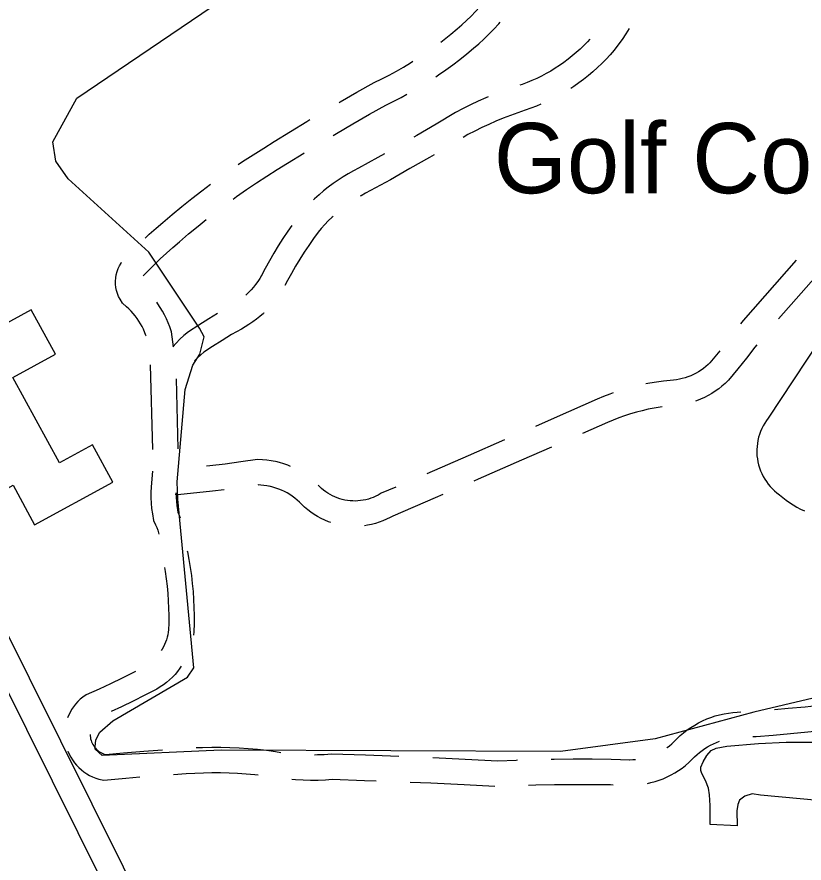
# Model space of a CAD drawing. Extents: x 3568792 to 3606828, y 529143 to 554785.
# Drawn here: x 3584735 to 3585665, y 535934 to 536934 of the extents above; entities that cross this region are included whole.
import ezdxf

# ---------------------------------------------------------------- set-up
doc = ezdxf.new("R2010")
doc.units = 0
for name, color, linetype in [('V-BLDG-IDEN', 7, 'Continuous'), ('V-BLDG-OTLN', 7, 'Continuous'), ('V-ROAD-CNTR', 7, 'Continuous'), ('V-SITE-OTLN', 7, 'Continuous'), ('V-TOPO-SHOR', 7, 'Continuous')]:
    doc.layers.add(name, color=color, linetype=linetype)

msp = doc.modelspace()

# ---------------------------------------------------------------- linework, layer by layer
at = {"layer": 'V-BLDG-OTLN'}
msp.add_lwpolyline([(3584785.2, 536406.99), (3584730.13, 536508), (3584780.53, 536535.47), (3584752.02, 536587.75), (3584649.36, 536531.78), (3584674.16, 536486.29), (3584666.89, 536482.33), (3584687.6, 536444.35), (3584659.96, 536429.28), (3584675.87, 536400.1), (3584697.16, 536411.71), (3584717.85, 536373.76), (3584730.38, 536380.59), (3584755.94, 536333.72), (3584848.35, 536384.12), (3584824.26, 536428.3)], close=True, dxfattribs=at)
at = {"layer": 'V-ROAD-CNTR'}
for p, q in [((3585700.82, 536652.21), (3585634.72, 536577.17)), ((3584892.56, 536522.77), (3584895.19, 536422.8)), ((3584923.01, 536506.15), (3584925.18, 536423.59))]:
    msp.add_line(p, q, dxfattribs=at)
for points in [[(3585235.77, 536904.14), (3585239.85, 536907.25), (3585247.44, 536913.3), (3585254.91, 536919.53), (3585260.63, 536924.48), (3585266.17, 536929.54), (3585271.57, 536934.75), (3585276.83, 536940.1), (3585281.94, 536945.59), (3585286.91, 536951.21), (3585291.73, 536956.96), (3585296.39, 536962.84), (3585300.89, 536968.84), (3585305.24, 536974.96), (3585305.43, 536975.25)], [(3585229.95, 536863.15), (3585233.17, 536865.29), (3585241.68, 536871.2), (3585250.05, 536877.3), (3585258.29, 536883.58), (3585266.4, 536890.04), (3585274.34, 536896.67), (3585280.57, 536902.07), (3585286.7, 536907.67), (3585292.68, 536913.43), (3585298.5, 536919.35), (3585304.16, 536925.42), (3585306.07, 536927.59)], [(3585458.36, 536920.27), (3585454.32, 536913.84), (3585449.86, 536907.14), (3585445.06, 536900.32), (3585440.41, 536894.57), (3585435.75, 536889.16), (3585430.93, 536883.9), (3585425.94, 536878.79), (3585420.8, 536873.84), (3585415.5, 536869.06), (3585410.06, 536864.44), (3585404.47, 536859.99), (3585398.75, 536855.72), (3585392.9, 536851.63), (3585389.24, 536849.24)], [(3585411.87, 536907.51), (3585409.13, 536904.52), (3585404.8, 536900.08), (3585400.33, 536895.79), (3585395.73, 536891.62), (3585391, 536887.61), (3585386.15, 536883.75), (3585381.19, 536880.04), (3585376.1, 536876.49), (3585370.91, 536873.11), (3585365.61, 536869.88), (3585360.22, 536866.82), (3585354.74, 536863.93), (3585349.16, 536861.21), (3585343.5, 536858.67), (3585337.77, 536856.31), (3585331.97, 536854.13), (3585329.19, 536853.19)], [(3585115.53, 536832.78), (3585116.91, 536833.58), (3585136.69, 536844.89), (3585156.88, 536856.15), (3585166.12, 536860.66), (3585174.75, 536865.11), (3585183.28, 536869.74), (3585191.7, 536874.56), (3585200.02, 536879.57), (3585202.89, 536881.38)], [(3585108.41, 536793.8), (3585112.52, 536796.26), (3585131.92, 536807.61), (3585151.44, 536818.76), (3585170.78, 536829.55), (3585179.58, 536833.84), (3585188.79, 536838.59), (3585195.77, 536842.39)], [(3585291.69, 536839.29), (3585289.05, 536838.2), (3585280, 536834.2), (3585271.04, 536830.01), (3585262.18, 536825.62), (3585253.19, 536820.9), (3585230.15, 536807.1), (3585207.41, 536793.75), (3585203.87, 536791.72)], [(3585353.95, 536830.53), (3585348.76, 536828.39), (3585342.08, 536825.89), (3585335.53, 536823.65), (3585326.62, 536820.64), (3585317.96, 536817.49), (3585309.37, 536814.15), (3585300.85, 536810.62), (3585292.42, 536806.89), (3585284.07, 536802.98), (3585275.81, 536798.89), (3585267.88, 536794.73), (3585262.16, 536791.31)], [(3584996.39, 536759.3), (3585001.62, 536762.84), (3585014.04, 536770.96), (3585026.6, 536778.88), (3585039.09, 536786.48), (3585058.26, 536798.48), (3585077.69, 536810.38), (3585081.1, 536812.42)], [(3584990.41, 536718.54), (3584994.59, 536721.57), (3585006.34, 536729.82), (3585018.23, 536737.86), (3585030.25, 536745.72), (3585042.4, 536753.38), (3585054.85, 536760.95), (3585074.05, 536772.98), (3585074.2, 536773.07)], [(3585169.1, 536771.93), (3585161.57, 536767.7), (3585138.59, 536755.05), (3585132.67, 536752.01), (3585126.47, 536748.55), (3585120.38, 536744.89), (3585114.41, 536741.03), (3585108.58, 536736.98), (3585102.88, 536732.73), (3585097.33, 536728.3), (3585091.92, 536723.7), (3585086.67, 536718.91), (3585085.49, 536717.77)], [(3585227.76, 536770.91), (3585222.47, 536767.81), (3585199.37, 536754.54), (3585176.15, 536741.48), (3585152.69, 536728.57), (3585146.84, 536725.56), (3585141.5, 536722.59), (3585140.54, 536722.01)], [(3584886.62, 536672.63), (3584891.43, 536677.08), (3584899.42, 536684.16), (3584907.4, 536690.94), (3584918.55, 536700.5), (3584929.98, 536709.98), (3584941.56, 536719.27), (3584953.28, 536728.37), (3584963.73, 536736.21)], [(3585108.49, 536698.21), (3585107.24, 536697.07), (3585102.85, 536692.8), (3585098.61, 536688.4), (3585094.52, 536683.85), (3585090.78, 536679.42), (3585085.34, 536671.88), (3585079.82, 536663.9), (3585074.47, 536655.8), (3585069.29, 536647.59), (3585064.27, 536639.28), (3585059.43, 536630.87), (3585054.77, 536622.36), (3585051.7, 536616.49)], [(3584884.07, 536627.82), (3584889.9, 536633.94), (3584896.98, 536641.06), (3584904.2, 536648.03), (3584911.57, 536654.84), (3584919.08, 536661.5), (3584926.88, 536668.12), (3584937.89, 536677.57), (3584948.95, 536686.74), (3584958.51, 536694.41)], [(3585059.6, 536687.4), (3585054.96, 536680.69), (3585049.27, 536672.08), (3585043.76, 536663.35), (3585038.43, 536654.52), (3585033.28, 536645.57), (3585028.31, 536636.51), (3585023.61, 536627.5)], [(3584505.19, 536679.96), (3584507.74, 536674.89), (3584712.16, 536227.43), (3584897.55, 535855.29), (3584898.16, 535848.58)], [(3584478.39, 536666.47), (3584480.69, 536661.91), (3584685.09, 536214.5), (3584867.43, 535848.48)], [(3584887.54, 536557), (3584887.35, 536557.58), (3584884.42, 536564.83), (3584882.86, 536568.03), (3584881.07, 536571.31), (3584879.13, 536574.5), (3584877.05, 536577.6), (3584874.82, 536580.6), (3584872.46, 536583.5), (3584869.97, 536586.28), (3584867.35, 536588.95), (3584864.61, 536591.48), (3584859.71, 536595.62), (3584856.84, 536600.2), (3584855.14, 536603.54), (3584853.74, 536607.03), (3584852.67, 536610.63), (3584851.92, 536614.31), (3584851.52, 536618.04), (3584851.44, 536621.79), (3584851.71, 536625.54), (3584852.32, 536629.24), (3584853.26, 536632.89), (3584854.53, 536636.42), (3584856.11, 536639.83), (3584858, 536643.08), (3584858.7, 536644.08)], [(3585655.67, 536646.35), (3585593, 536575.2), (3585589.88, 536571.06)], [(3585024.13, 536628.42), (3585021.8, 536624.62), (3585019.49, 536621.2), (3585017.03, 536617.87), (3585014.44, 536614.65), (3585011.71, 536611.55), (3585008.86, 536608.56), (3585005.87, 536605.69), (3585005.27, 536605.16)], [(3584919.92, 536544.15), (3584917.5, 536561.87), (3584915.55, 536567.86), (3584911.85, 536577.03), (3584909.53, 536581.79), (3584907.07, 536586.29), (3584904.41, 536590.67), (3584901.56, 536594.92), (3584900.1, 536596.88)], [(3584971.85, 536583.36), (3584961.6, 536577.19), (3584949.91, 536569.85), (3584937.67, 536561.84), (3584932.32, 536557.27), (3584927.63, 536552.97), (3584923.1, 536548.5), (3584919.06, 536544.21)], [(3585026.74, 536584.14), (3585026.2, 536583.62), (3585022.15, 536580.04), (3585017.95, 536576.64), (3585013.61, 536573.42), (3585009.14, 536570.39), (3585004.54, 536567.55), (3585000.18, 536565.1), (3584988.66, 536558.46), (3584977.31, 536551.63), (3584966.09, 536544.59), (3584955.69, 536537.79), (3584952.2, 536534.81), (3584948.32, 536531.24), (3584944.65, 536527.62)], [(3585565.36, 536539.46), (3585563.25, 536536.81), (3585553.59, 536525.1), (3585551.44, 536523.04), (3585548.81, 536520.75), (3585546.07, 536518.6), (3585543.22, 536516.58), (3585540.28, 536514.7), (3585537.26, 536512.97), (3585534.15, 536511.39), (3585530.97, 536509.96), (3585527.72, 536508.69), (3585524.41, 536507.57), (3585521.06, 536506.62), (3585517.66, 536505.84), (3585514.23, 536505.22), (3585510.77, 536504.77), (3585506.75, 536504.44), (3585498.71, 536503.6), (3585490.66, 536502.52), (3585482.63, 536501.19), (3585477.98, 536500.28)], [(3585609.01, 536546.57), (3585606.84, 536543.69), (3585596.79, 536530.72), (3585586.54, 536517.9), (3585575.61, 536504.64), (3585571.66, 536500.86), (3585567.92, 536497.62), (3585564.03, 536494.56), (3585559.99, 536491.69), (3585555.82, 536489.03), (3585551.52, 536486.57), (3585547.11, 536484.32), (3585542.59, 536482.29), (3585537.98, 536480.49), (3585536.73, 536480.07)], [(3585439.45, 536489.69), (3585435.64, 536488.33), (3585428.06, 536485.39), (3585420.67, 536482.26), (3585369.8, 536459.83), (3585347.63, 536450.11)], [(3585497.46, 536473.16), (3585495.1, 536472.84), (3585487.96, 536471.66), (3585480.85, 536470.27), (3585473.78, 536468.67), (3585466.77, 536466.87), (3585459.81, 536464.85), (3585452.92, 536462.63), (3585446.09, 536460.21), (3585439.34, 536457.59), (3585432.57, 536454.72), (3585402.99, 536441.68)], [(3585310.99, 536434.07), (3585268.14, 536415.41), (3585219.26, 536394.26)], [(3585366.38, 536425.57), (3585331.01, 536410.07), (3585280.09, 536387.89), (3585274.73, 536385.57)], [(3585040.05, 536408.61), (3585035.41, 536409.52), (3585030.35, 536410.25), (3585025.26, 536410.73), (3585019.08, 536411), (3584999.35, 536408.08), (3584981.11, 536405.62), (3584962.83, 536403.4), (3584958.91, 536402.98)], [(3585058.04, 536402.9), (3585055.1, 536404.12), (3585050.28, 536405.83), (3585045.39, 536407.31), (3585040.79, 536408.45)], [(3584895.15, 536397.14), (3584893.5, 536378.54), (3584893.23, 536372.19), (3584893.24, 536365.82), (3584893.55, 536359.46), (3584894.14, 536353.13), (3584895.01, 536346.83), (3584896.47, 536339.01), (3584898.88, 536333.87), (3584900.18, 536330.73), (3584901.32, 536327.53), (3584902.3, 536324.29), (3584902.71, 536322.67)], [(3585034.3, 536379.17), (3585030.38, 536379.93), (3585026.79, 536380.45), (3585023.19, 536380.79), (3585020.64, 536380.9), (3585019.59, 536380.75)], [(3585105.96, 536336.54), (3585102.96, 536337.57), (3585098.59, 536339.34), (3585094.33, 536341.34), (3585090.18, 536343.56), (3585086.15, 536346), (3585082.25, 536348.66), (3585078.51, 536351.51), (3585074.92, 536354.56), (3585071.62, 536357.68), (3585068.64, 536360.68), (3585065.97, 536363.12), (3585063.17, 536365.42), (3585060.26, 536367.59), (3585057.26, 536369.6), (3585054.15, 536371.47), (3585050.95, 536373.18), (3585047.68, 536374.72), (3585044.33, 536376.11), (3585040.92, 536377.32), (3585037.45, 536378.37), (3585033.57, 536379.33)], [(3585182.51, 536378.45), (3585165.47, 536371.12), (3585161.68, 536368.95), (3585158.9, 536367.55), (3585156.05, 536366.3), (3585153.14, 536365.2), (3585150.17, 536364.26), (3585147.16, 536363.47), (3585144.11, 536362.85), (3585141.04, 536362.4), (3585137.93, 536362.1), (3585134.82, 536361.97), (3585131.71, 536362.01), (3585128.61, 536362.22), (3585125.52, 536362.58), (3585122.45, 536363.12), (3585119.42, 536363.81), (3585116.42, 536364.67), (3585113.48, 536365.68), (3585110.6, 536366.85), (3585107.78, 536368.17), (3585105.03, 536369.64), (3585102.38, 536371.25), (3585099.81, 536373), (3585097.33, 536374.89), (3585094.96, 536376.9), (3585092.58, 536379.16), (3585091.02, 536380.73)], [(3584979.97, 536375.26), (3584966.25, 536373.6), (3584947.56, 536371.57), (3584928.84, 536369.79), (3584922.8, 536369.3), (3584923.23, 536371.57), (3584923.24, 536366.57), (3584923.48, 536361.58), (3584923.94, 536356.59), (3584924.63, 536351.64), (3584925.26, 536348.28), (3584926.35, 536345.97), (3584927.95, 536342.06)], [(3585238.02, 536369.69), (3585229.11, 536365.83), (3585178.9, 536344.24), (3585175.91, 536342.53), (3585171.7, 536340.4), (3585167.38, 536338.51), (3585162.98, 536336.85), (3585158.49, 536335.42), (3585153.93, 536334.24), (3585149.31, 536333.3), (3585145.43, 536332.72)], [(3584936.21, 536303.09), (3584936.43, 536302.06), (3584938.2, 536292.76), (3584939.75, 536283.41), (3584941.08, 536274.04), (3584942.18, 536264.63), (3584943.06, 536255.19), (3584943.7, 536245.75), (3584944.13, 536236.28), (3584944.32, 536226.81), (3584944.29, 536217.34), (3584944.01, 536207.28), (3584943.54, 536203.68)], [(3584909.36, 536283.3), (3584910.1, 536278.86), (3584911.33, 536270.19), (3584912.34, 536261.5), (3584913.15, 536252.78), (3584913.75, 536244.05), (3584914.14, 536235.3), (3584914.32, 536226.56), (3584914.29, 536217.8), (3584914.07, 536209.65), (3584913.72, 536207.03), (3584913.17, 536204.04), (3584912.46, 536201.09), (3584911.59, 536198.18), (3584910.58, 536195.31), (3584909.42, 536192.51), (3584908.11, 536189.77), (3584906.66, 536187.1), (3584905.52, 536185.25)], [(3584874.93, 536160.44), (3584872.59, 536159.22), (3584859.22, 536152.54), (3584845.73, 536146.09), (3584832.13, 536139.89), (3584816.81, 536133.22), (3584812.74, 536130.27), (3584809.72, 536127.74), (3584806.9, 536125.01), (3584804.27, 536122.08), (3584801.86, 536118.98), (3584799.67, 536115.7), (3584797.73, 536112.28), (3584796.03, 536108.73), (3584794.84, 536105.72)], [(3584929.23, 536166.7), (3584927.61, 536164.36), (3584924.8, 536160.7), (3584921.81, 536157.21), (3584918.63, 536153.86), (3584915.29, 536150.69), (3584911.78, 536147.7), (3584908.12, 536144.91), (3584904.32, 536142.3), (3584900.29, 536139.84), (3584886.24, 536132.5), (3584872.39, 536125.58), (3584858.43, 536118.91), (3584846.27, 536113.36)], [(3585630.03, 536115.78), (3585646.26, 536117.15), (3585666.3, 536119.02), (3585686.33, 536121.06), (3585706.14, 536123.26), (3585712.66, 536124.21), (3585719.19, 536125.37), (3585725.69, 536126.71), (3585729.24, 536127.56)], [(3585502.67, 536070.4), (3585503.05, 536070.66), (3585505.9, 536072.89), (3585508.64, 536075.26), (3585511.33, 536077.83), (3585514.6, 536081.19), (3585518.49, 536084.83), (3585522.55, 536088.28), (3585526.78, 536091.52), (3585531.16, 536094.56), (3585535.68, 536097.39), (3585540.33, 536099.99), (3585545.1, 536102.36), (3585549.98, 536104.5), (3585554.96, 536106.4), (3585560.02, 536108.06), (3585565.16, 536109.47), (3585570.36, 536110.64), (3585575.61, 536111.55), (3585580.9, 536112.21), (3585585.91, 536112.58), (3585590.14, 536112.87)], [(3585604.4, 536083.75), (3585608.26, 536084.01), (3585628.59, 536085.55), (3585648.91, 536087.27), (3585669.22, 536089.16), (3585689.5, 536091.23), (3585703.97, 536092.83)], [(3584821.46, 536086.16), (3584821.55, 536084.46), (3584821.77, 536082.67), (3584822.12, 536080.91), (3584822.59, 536079.18), (3584823.19, 536077.48), (3584823.9, 536075.83), (3584824.73, 536074.23), (3584825.67, 536072.7), (3584826.72, 536071.24), (3584827.87, 536069.86), (3584829.11, 536068.56), (3584830.45, 536067.35), (3584831.86, 536066.24), (3584833.35, 536065.24), (3584834.91, 536064.34), (3584836.52, 536063.56), (3584838.19, 536062.9), (3584839.91, 536062.35), (3584839.72, 536062.4), (3584861.06, 536064.47), (3584885.01, 536066.53), (3584907, 536068.18)], [(3585479.8, 536028.39), (3585483.99, 536029.29), (3585488.95, 536030.62), (3585493.83, 536032.19), (3585498.63, 536034.01), (3585503.32, 536036.07), (3585507.91, 536038.35), (3585512.38, 536040.87), (3585516.71, 536043.6), (3585520.91, 536046.55), (3585524.95, 536049.7), (3585528.83, 536053.05), (3585532.46, 536056.53), (3585535.61, 536059.77), (3585538.44, 536062.42), (3585541.4, 536064.92), (3585544.48, 536067.29), (3585547.67, 536069.5), (3585550.95, 536071.56), (3585554.34, 536073.45), (3585557.82, 536075.18), (3585561.37, 536076.74), (3585564.96, 536078.11)], [(3584946.92, 536070.67), (3584954.32, 536070.97), (3584965.11, 536071.19), (3584975.91, 536071.16), (3584986.71, 536070.9), (3584997.49, 536070.4), (3585008.27, 536069.67), (3585019.02, 536068.7), (3585029.75, 536067.5), (3585040.45, 536066.06), (3585046.59, 536065.1)], [(3584795.22, 536066.59), (3584795.23, 536066.55), (3584796.79, 536062.93), (3584798.61, 536059.45), (3584800.66, 536056.09), (3584802.96, 536052.9), (3584805.47, 536049.87), (3584808.19, 536047.03), (3584811.11, 536044.39), (3584814.21, 536041.96), (3584817.47, 536039.76), (3584820.88, 536037.8), (3584824.43, 536036.09), (3584828.08, 536034.63), (3584831.83, 536033.44), (3584837.58, 536032.05), (3584863.79, 536034.59), (3584880.29, 536036.01)], [(3585086.44, 536062.35), (3585089.95, 536062.38), (3585097.83, 536062.7), (3585106.72, 536063.33), (3585146.79, 536062.01), (3585186.12, 536060.54), (3585186.37, 536060.53)], [(3585226.33, 536058.86), (3585264.74, 536057.09), (3585303.32, 536055.16), (3585324.93, 536056.03), (3585326.22, 536056.07)], [(3585366.21, 536057.06), (3585369.69, 536057.13), (3585392.07, 536057.32), (3585414.46, 536057.26), (3585436.84, 536056.96), (3585459.14, 536056.43)], [(3585458.6, 536056.43), (3585462.59, 536056.48), (3585465.65, 536056.67)], [(3584920.17, 536038.98), (3584934.82, 536039.92), (3584945.09, 536040.57), (3584955.23, 536040.99), (3584965.37, 536041.19), (3584975.51, 536041.16), (3584985.65, 536040.91), (3584995.78, 536040.45), (3585005.9, 536039.76), (3585016, 536038.85), (3585020, 536038.4)], [(3585059.67, 536033.35), (3585064.23, 536032.97), (3585073.05, 536032.5), (3585081.87, 536032.31), (3585090.69, 536032.39), (3585099.5, 536032.74), (3585107.29, 536033.3), (3585145.74, 536032.03), (3585159.58, 536031.51)], [(3585199.55, 536029.95), (3585224.12, 536028.93), (3585263.3, 536027.13), (3585299.44, 536025.31)], [(3585339.41, 536026.45), (3585348.04, 536026.71), (3585370.1, 536027.13), (3585392.16, 536027.31), (3585414.22, 536027.26), (3585436.28, 536026.97), (3585439.4, 536026.89)]]:
    msp.add_lwpolyline(points, dxfattribs=at)
at = {"layer": 'V-SITE-OTLN'}
msp.add_lwpolyline([(3585809.07, 536160.47), (3585605.41, 536112.71), (3585489.03, 536081.14), (3585377.22, 536065.91), (3584976.46, 536067.62), (3584835.59, 536061.54), (3584827.43, 536068.83), (3584827.43, 536071.55), (3584828.36, 536079.73), (3584832.92, 536088.81), (3584848.4, 536102.41), (3584936.65, 536154.04), (3584943.94, 536164.92), (3584925.25, 536363.98), (3584924.42, 536384.48), (3584933.73, 536493.52), (3584942.87, 536522.58), (3584951.08, 536535.28), (3584956.1, 536555.98), (3584950.67, 536565.98), (3584890.92, 536656.05), (3584795.67, 536742.57), (3584781.17, 536763.51), (3584777.58, 536786.23), (3584805.85, 536837.97), (3585088.86, 537030.07)], dxfattribs=at)
at = {"layer": 'V-TOPO-SHOR'}
msp.add_line((3585585.61, 535996.03), (3585585.97, 535978.4), dxfattribs=at)
for points in [[(3585742.1, 536641.08), (3585622.69, 536459.91), (3585620.5, 536456.98), (3585618.48, 536453.93), (3585616.65, 536450.76), (3585615, 536447.49), (3585613.54, 536444.14), (3585612.29, 536440.7), (3585611.23, 536437.2), (3585610.39, 536433.64), (3585609.74, 536430.04), (3585609.31, 536426.41), (3585609.1, 536422.76), (3585609.09, 536419.1), (3585609.3, 536415.44), (3585609.72, 536411.81), (3585610.35, 536408.21), (3585611.19, 536404.65), (3585612.24, 536401.14), (3585613.49, 536397.7), (3585614.93, 536394.34), (3585616.57, 536391.07), (3585618.4, 536387.9), (3585620.41, 536384.84), (3585622.59, 536381.91), (3585624.94, 536379.1), (3585627.45, 536376.44), (3585630.11, 536373.93), (3585632.92, 536371.58), (3585635.85, 536369.39), (3585639.69, 536366.12), (3585643.67, 536363.02), (3585647.78, 536360.1), (3585652.02, 536357.37), (3585656.37, 536354.83), (3585660.84, 536352.48), (3585665.4, 536350.34)], [(3585585.97, 535978.4), (3585553.85, 535980.03), (3585553.89, 536002.36), (3585553.13, 536014.89), (3585551.97, 536022.73), (3585548.46, 536031.74), (3585544.16, 536039.98), (3585542.99, 536043.51), (3585543, 536047.43), (3585545.75, 536054.08), (3585550.08, 536061.52), (3585555.18, 536067.38), (3585561.06, 536070.11), (3585573.6, 536072.45), (3585611.21, 536075.51), (3585643.73, 536077.02), (3585675.07, 536076.97)], [(3585707.07, 536006.01), (3585613.46, 536014.4), (3585603.67, 536015.98), (3585595.04, 536013.25), (3585588.77, 536008.56), (3585586.8, 536003.47), (3585585.61, 535996.03)]]:
    msp.add_lwpolyline(points, dxfattribs=at)

# ---------------------------------------------------------------- texts
at = {"layer": 'V-BLDG-IDEN'}
msp.add_text('Golf Course', height=82.9998, dxfattribs=at).set_placement((3585298.42, 536725.49))

doc.saveas('drawing.dxf')
